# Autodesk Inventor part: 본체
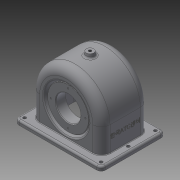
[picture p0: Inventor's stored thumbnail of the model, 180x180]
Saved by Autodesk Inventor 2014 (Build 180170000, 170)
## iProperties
Created: 2015-09
Part Number: 본체
Material: 일반
Document SubType Name: Modeling
Designer: basic
Density: 1 g/cm^3
Appearance: 기본값
Author: basic
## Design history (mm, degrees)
sketch "스케치1"
  geometry: L1 (-70, -52)-(70, -52); L2 (70, -52)-(70, 52); L3 (70, 52)-(-70, 52); L4 (-70, 52)-(-70, -52); L5 (-70, -52)-(70, 52); 2 further points
  constraints: 10 end point, 2 parallel, 1 coincident, 1 horizontal, 1 midpoint, 1 perpendicular
  dimensions: "d0" = 104 distance of L3.end L1.start; "d1" = 140 distance of L1.start L1.end
extrude "돌출1" new body sketch "스케치1" distance "d2" = 7; taper "d3" = 0 deg
sketch "스케치2"
  geometry: L1 (-70, 0)-(-70, 7) reference; L2 (-70, 7)-(70, 7) reference; L3 (70, 7)-(70, 0) reference; L4 (70, 0)-(-70, 0) reference; L5 (57, 7)-(-57, 7); L6 (57, 7)-(57, 47); L7 (-57, 7)-(-57, 47); L8 (57, 47)-(-57, 47); A1 r 57 centre (0, 47) between (57, 47) and (-57, 47); 2 further points
  constraints: 8 end point, 3 midpoint, 2 parallel, 2 point on circle, 1 centre point, 1 perpendicular
  dimensions: "d4" = 114 distance of L5.start L5.end; "d5" = 40 distance of L5.start L6.end; "d6" = 40 distance of L5.end L7.end
extrude "돌출2" join sketch "스케치2" stored distance "d7" = 77; taper "d8" = 0 deg
feature "쉘2" dims "d10" = 5
sketch "스케치3"
  geometry: L1 (117, 13.5)-(117, 80.5) reference; L2 (130, 0)-(0, 0) reference; L3 (130, 0)-(130, 94) reference; L4 (130, 94)-(0, 94) reference; L5 (0, 94)-(0, 0) reference; L6 (0, 0)-(130, 0) reference; L7 (135, 99)-(135, -5) reference; L8 (135, -5)-(-5, -5) reference; L9 (-5, -5)-(-5, 99) reference; L10 (-5, 99)-(135, 99) reference; L11 (135, -5)-(-5, -5) reference; L12 (130, 94)-(130, 0) reference; L13 (130, 0)-(0, 0) reference; L14 (0, 0)-(0, 94) reference; L15 (0, 94)-(130, 94) reference; L16 (135, -5)-(-5, -5) reference; L17 (135, 99)-(135, -5) reference; L18 (-5, 99)-(135, 99) reference; L19 (-5, -5)-(-5, 99) reference; L20 (0, 0)-(130, 0); L21 (130, 0)-(130, 94); L22 (130, 94)-(0, 94); L23 (0, 94)-(0, 0); L24 (0, 0)-(130, 94); L25 (13, 13.5)-(117, 13.5) reference; L26 (117, 13.5)-(117, 80.5) reference; L27 (117, 80.5)-(13, 80.5) reference; L28 (13, 80.5)-(13, 13.5) reference; 4 further points
  constraints: 10 end point, 2 parallel, 1 coincident, 1 horizontal, 1 midpoint, 1 perpendicular
  dimensions: "d11" = 130 distance of L20.start L20.end; "d12" = 94 distance of L22.end L20.start
extrude "돌출3" join sketch "스케치3" distance "d13" = 2; taper "d14" = 0 deg
node "작업 평면1"
sketch "스케치4"
  geometry: L1 (70, 47)-(70, 40) reference; L2 (70, 40)-(57, 40) reference; L3 (57, 40)-(57, 0) reference; L4 (-57, 0)-(-57, 40) reference; L5 (-57, 40)-(-70, 40) reference; L6 (-70, 40)-(-70, 47) reference; L7 (-70, 47)-(-52, 47) reference; L8 (-52, 47)-(-52, 0) reference; L9 (52, 0)-(52, 47) reference; L10 (52, 47)-(70, 47) reference; C1 r 28 at (0, 0); A1 r 57 centre (0, 0) between (-57, 0) and (57, 0) reference; A2 r 52 centre (0, 0) between (-52, 0) and (52, 0) reference; 1 further point
  constraints: 1 centre point, 1 coincident
  dimensions: "d16" = 56 diameter of C1
extrude "돌출4" join sketch "스케치4" distance "d17" = 16; taper "d18" = 40 deg
sketch "스케치6"
  geometry: L1 (-70, 0)-(-70, 7) reference; L2 (-70, 7)-(-57, 7) reference; L3 (-57, 7)-(-57, 47) reference; L4 (57, 47)-(57, 7) reference; L5 (57, 7)-(70, 7) reference; L6 (70, 7)-(70, 0) reference; L7 (70, 0)-(52, 0) reference; L8 (52, 0)-(52, 47) reference; L9 (-52, 47)-(-52, 0) reference; L10 (-52, 0)-(-70, 0) reference; L11 (51, 47)-(51, -1); L12 (51, -1)-(71, -1); L13 (71, -1)-(71, 8); L14 (71, 8)-(58, 8); L15 (58, 8)-(58, 47); L16 (-58, 47)-(-58, 8); L17 (-58, 8)-(-71, 8); L18 (-71, 8)-(-71, -1); L19 (-71, -1)-(-51, -1); L20 (-51, -1)-(-51, 47); L21 (52, 0)-(51, 0); L22 (-52, 0)-(-51, 0); A1 r 57 centre (0, 47) between (57, 47) and (-57, 47) reference; A2 r 52 centre (0, 47) between (52, 47) and (-52, 47) reference; A3 r 51 centre (0, 47) between (51, 47) and (-51, 47); A4 r 58 centre (0, 47) between (58, 47) and (-58, 47); 1 further point
  constraints: 24 end point, 4 point on circle, 2 centre point, 2 point on line, 1 collinear, 1 perpendicular, 11 other
  dimensions: "d22" = 1 radial gap between concentric circles of A3 A2
extrude "돌출6" join sketch "스케치6" stored distance "d23" = 67; taper "d24" = 0 deg
node "작업 평면2"
sketch "스케치8"
  geometry: L1 (70, 47)-(70, 40) reference; L2 (70, 40)-(57, 40) reference; L3 (57, 40)-(57, 0) reference; L4 (-57, 0)-(-57, 40) reference; L5 (-57, 40)-(-70, 40) reference; L6 (-70, 40)-(-70, 47) reference; L7 (-70, 47)-(-51, 47) reference; L8 (-51, 47)-(51, 47) reference; L9 (51, 47)-(70, 47) reference; L10 (-51, 47)-(-51, 0) reference; L11 (51, 0)-(51, 47) reference; C1 r 39.747 at (0, 0) reference; C2 r 33 at (0, 0); A1 r 57 centre (0, 0) between (-57, 0) and (57, 0) reference; A2 r 51 centre (0, 0) between (-51, 0) and (51, 0) reference; 1 further point
  constraints: 1 centre point, 1 coincident
  dimensions: "d27" = 66 diameter of C2
extrude "돌출7" cut sketch "스케치8" distance "d28" = 5; taper "d29" = 40 deg
sketch "스케치9"
  geometry: C1 r 33 at (0, 0) reference; C2 r 33 at (0, 0); 1 further point
  constraints: 1 centre point, 1 coincident
  dimensions: "d30" = 66 diameter of C2
extrude "돌출8" join sketch "스케치9" distance "d31" = 2; taper "d32" = 0 deg
sketch "스케치10"
  geometry: C1 r 33 at (0, 0) reference; C2 r 20 at (0, 0); 1 further point
  constraints: 1 centre point, 1 coincident
  dimensions: "d33" = 40 diameter of C2
extrude "돌출9" cut sketch "스케치10" distance "d34" = 16; taper "d35" = 0 deg
sketch "스케치11"
  geometry: C1 r 31 at (0, -47); A1 r 57 centre (0, -47) between (-57, -47) and (57, -47) reference; 1 further point
  constraints: 1 centre point, 1 coincident
  dimensions: "d36" = 62 diameter of C1
extrude "돌출10" join sketch "스케치11" distance "d37" = 10; taper "d38" = 0 deg
sketch "스케치12"
  geometry: C1 r 31 at (0, 0) reference; C2 r 20 at (0, 0); 1 further point
  constraints: 1 centre point, 1 coincident
  dimensions: "d39" = 40 diameter of C2
extrude "돌출11" cut sketch "스케치12" distance "d40" = 15; taper "d41" = 0 deg
node "작업 평면3"
sketch "스케치13"
  geometry: L1 (57, -38.5)-(57, 38.5) reference; L2 (-57, 38.5)-(57, 38.5) reference; L3 (-57, -38.5)-(-57, 38.5) reference; L4 (57, -38.5)-(-57, -38.5) reference; C1 r 6 at (0, 0); 1 further point
  constraints: 1 centre point, 1 coincident
  dimensions: "d43" = 12 diameter of C1
extrude "돌출12" join sketch "스케치13" stored distance "d44" = 15; taper "d45" = 10 deg
sketch "스케치14"
  geometry: C1 r 6 at (0, 0) reference; 1 further point
  constraints: 1 coincident
hole "구멍1" sketch "스케치14" at (0, 0) diameter "d46" = 4.459; stored, may be unused: countersink angle "d50" = 90 deg, drill point angle "d52" = 0 deg; dims "d47" = 12, "d48" = 4, "d49" = 2, "d51" = 8
sketch "스케치15" dims "d53" = 56
  geometry: C1 r 33 at (0, 0) reference; 3 further points
  constraints: 1 coincident, 1 vertical alignment, 2 other
hole "구멍2" sketch "스케치15" at (0, 28) diameter "d54" = 2.459; stored, may be unused: countersink angle "d58" = 90 deg, drill point angle "d60" = 118 deg; dims "d55" = 7, "d56" = 4, "d57" = 2, "d59" = 9
sketch "스케치16" dims "d64" = 48
  geometry: C1 r 31 at (0, 0) reference; 3 further points
  constraints: 1 coincident, 1 vertical alignment, 2 other
hole "구멍3" sketch "스케치16" at (0, -24) diameter "d65" = 2.459; stored, may be unused: countersink angle "d69" = 90 deg, drill point angle "d71" = 118 deg; dims "d66" = 6, "d67" = 4, "d68" = 2, "d70" = 8
fillet "모깎기1" dims "d75" = 0.5
sketch "스케치17"
  geometry: L1 (70, -52)-(70, 52) reference; L2 (58, -39.5)-(58, 39.5) reference; L3 (58, 0)-(70, 0); C1 r 2.5 at (62, 44); C2 r 2.5 at (62, 0); 1 further point
  constraints: 2 centre point, 2 end point, 2 midpoint
  dimensions: "d77" = 8 distance from line of L1 C1.centre; "d78" = 5 diameter of C1; "d79" = 44 distance from line of L3 C1.centre; "d80" = 5 diameter of C2; "d81" = 8 distance from line of L1 C2.centre; "d82" = 44 distance of C1.centre C2.centre
extrude "돌출13" cut sketch "스케치17" stored distance "d83" = 15; taper "d84" = 0 deg
sketch "스케치18"
  geometry: L1 (40, 77)-(40, 90.5) reference; L2 (40, 90.5)-(47, 90.5) reference; L3 (47, 90.5)-(47, -13.5) reference; L4 (47, -13.5)-(40, -13.5) reference; L5 (40, -13.5)-(40, 0) reference; L6 (40, 0)-(0, 0) reference; L7 (0, 0)-(0, 77) reference; L8 (0, 77)-(40, 77) reference; L9 (47, 38.5)-(17, 38.5); L10 (40, 0)-(40, 77) reference; 1 further point
  constraints: 2 end point, 1 coincident, 1 parallel, 1 other
  dimensions: "d85" = 30 distance of L9.start L9.end
feature "엠보싱1" sketch "스케치18" dims "d10" = 5, "d86" = 0.5, "d87" = 0
fillet "모깎기3" dims "d88" = 9
fillet "모깎기4" dims "d89" = 14
fillet "모깎기5" dims "d90" = 1
fillet "모깎기6" dims "d91" = 7
fillet "모깎기7" dims "d92" = 3
fillet "모깎기8" dims "d93" = 3
chamfer "모따기1" distance "d94" = 1; stored, may be unused: second distance "d95" = 2, angle "d96" = 45 deg
fillet "모깎기9" dims "d97" = 3
node "솔리드1"
pattern_circular "원형 패턴1" dims angle "d62" = 360 deg
pattern_circular "원형 패턴2" dims angle "d73" = 360 deg
mirror "대칭1"
mirror "대칭2"
node "투영된 루프1"
node "투영된 루프2"
node "절단 모서리 투영1"
node "절단 모서리 투영2"
node "절단 모서리 투영3"
node "절단 모서리 투영4"
node "절단 모서리 투영5"
node "절단 모서리 투영6"
other parameters: "d15" = 14, "d26" = 0
